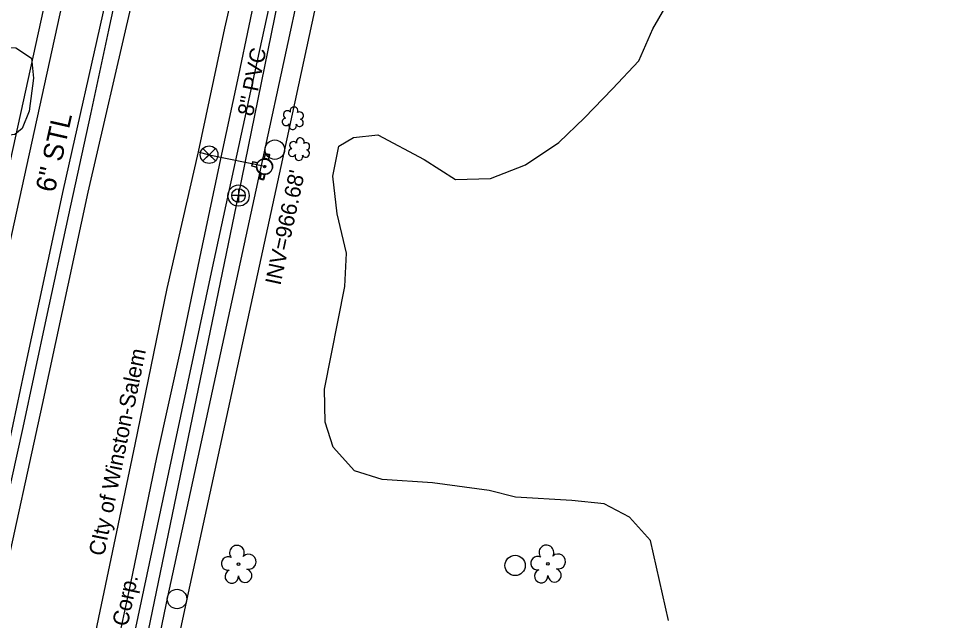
# Model space of a CAD drawing. Extents: x 1614427 to 1617186, y 896524 to 905462.
# Drawn here: x 1616435.3 to 1616671.9, y 900797.8 to 900949.7 of the extents above; entities that cross this region are included whole.
import ezdxf

# ---------------------------------------------------------------- set-up
doc = ezdxf.new("R2010")
doc.units = 0
for name, color, linetype in [('Exist Other Culture Well CELL', 7, 'Continuous'), ('Exist Roads EOP', 7, 'Continuous'), ('Exist Utilities Gas UG Line SUE LOS B', 7, 'Continuous'), ('Exist Utilities Gas UG Line SUE LOS B Text', 7, 'Continuous'), ('Exist Utilities Other Pole CELL', 7, 'Continuous'), ('Exist Utilities Power UG Cable SUE LOS D', 7, 'Continuous'), ('Exist Utilities Sanitary Sewer AG Line Invert Elevation', 7, 'Continuous'), ('Exist Utilities Sanitary Sewer Manhole CELL', 7, 'Continuous'), ('Exist Utilities Sanitary Sewer UG Line', 7, 'Continuous'), ('Exist Utilities Sanitary Sewer UG Line Text', 7, 'Continuous'), ('Exist Utilities Telephone UG Cable SUE LOS B', 7, 'Continuous'), ('Exist Utilities Telephone UG FO SUE LOS B', 7, 'Continuous'), ('Exist Utilities Telephone UG FO SUE LOS B Text', 7, 'Continuous'), ('Exist Utilities Telephone UG FO SUE LOS D', 7, 'Continuous'), ('Exist Utilities TV UG FO Cable SUE LOS D', 7, 'Continuous'), ('Exist Utilities Water Fire Hydrant CELL', 7, 'Continuous'), ('Exist Utilities Water UG Line SUE LOS B', 7, 'Continuous'), ('Exist Utilities Water UG Line SUE LOS B Text', 7, 'Continuous'), ('Exist Utilities Water Valve CELL', 7, 'Continuous'), ('Exist Vegetation Hedge Row', 7, 'Continuous'), ('Exist Vegetation Shrub CELL', 7, 'Continuous'), ('Exist Vegetation Tree CELL', 7, 'Continuous'), ('Exist Vegetation Woods Line', 7, 'Continuous')]:
    doc.layers.add(name, color=color, linetype=linetype)

msp = doc.modelspace()

# ---------------------------------------------------------------- linework, layer by layer
at = {"layer": 'Exist Other Culture Well CELL'}
msp.add_circle((1616560.59, 900811.64), 2.56, dxfattribs=at)
at = {"layer": 'Exist Roads EOP'}
for points in [[(1616506.95, 901008.01), (1616504.02, 900996.97), (1616501.39, 900985.55), (1616496, 900960.38), (1616490.77, 900935.39), (1616486.24, 900914.29), (1616481.23, 900890.84), (1616476.26, 900867), (1616470.04, 900838.9), (1616463.48, 900807.17), (1616456.7, 900775.38), (1616450.29, 900746.19), (1616449.34, 900741.63)], [(1616430.84, 900821.33), (1616436.39, 900846.5), (1616442.3, 900874.05), (1616447.95, 900900.18), (1616453.52, 900925.57), (1616457.99, 900946.8), (1616463.22, 900971)]]:
    msp.add_lwpolyline(points, dxfattribs=at)
at = {"layer": 'Exist Utilities Gas UG Line SUE LOS B'}
msp.add_lwpolyline([(1616457.16, 900954), (1616446.5, 900906.58), (1616436.54, 900860.35), (1616425.39, 900807.83), (1616416.23, 900761.6), (1616413.42, 900748.01), (1616411.61, 900739.4), (1616399.49, 900682.3), (1616394.55, 900660.9), (1616391.55, 900647.56), (1616383.19, 900606.2), (1616371.67, 900559.03), (1616360.02, 900508.87), (1616351.28, 900469.28), (1616341.84, 900429.49), (1616331.7, 900383.47)], dxfattribs=at)
at = {"layer": 'Exist Utilities Other Pole CELL'}
for centre in [(1616499.94, 900916.61), (1616475.24, 900803.17)]:
    msp.add_circle(centre, 2.46, dxfattribs=at)
at = {"layer": 'Exist Utilities Power UG Cable SUE LOS D'}
msp.add_line((1616444.89, 900672.03), (1616472.94, 900803.7), dxfattribs=at)
msp.add_lwpolyline([(1616472.94, 900803.7), (1616497.54, 900917.27), (1616543.86, 901131.07), (1616567.27, 901236.77), (1616608.79, 901427.38), (1616667.35, 901702.61)], dxfattribs=at)
at = {"layer": 'Exist Utilities Sanitary Sewer Manhole CELL'}
msp.add_lwpolyline([(1616490.77, 900906.73), (1616490.77, 900903.3), (1616490.77, 900905.02), (1616492.49, 900905.02), (1616489.06, 900905.02)], dxfattribs=at)
for radius in [2.69, 1.71]:
    msp.add_circle((1616490.77, 900905.02), radius, dxfattribs=at)
at = {"layer": 'Exist Utilities Sanitary Sewer UG Line'}
msp.add_lwpolyline([(1616444.8, 900682.93), (1616490.78, 900905.02), (1616557.11, 901230.35), (1616512.18, 901240.77), (1616568.35, 901492.88)], dxfattribs=at)
at = {"layer": 'Exist Utilities Telephone UG Cable SUE LOS B'}
msp.add_lwpolyline([(1616503.04, 901208.05), (1616504.34, 901207.7), (1616513.47, 901204.29), (1616516.02, 901201.09), (1616509.49, 901166.04), (1616502.86, 901137.25), (1616493.6, 901093.66), (1616483.21, 901045.76), (1616472.94, 900998.19), (1616463.74, 900953.48), (1616452.75, 900905.89), (1616441.22, 900852.26), (1616431.02, 900805.67), (1616418.45, 900757.41), (1616403.67, 900741.28), (1616397.61, 900729.94), (1616386.99, 900684.21), (1616386.12, 900682.91)], dxfattribs=at)
at = {"layer": 'Exist Utilities Telephone UG FO SUE LOS B'}
msp.add_lwpolyline([(1616504.35, 900979.92), (1616494.25, 900933.3), (1616484.09, 900886.8), (1616474.48, 900841.84), (1616464.75, 900795.88), (1616454.35, 900748.64), (1616444.4, 900703.78), (1616437.64, 900664.03), (1616423.47, 900606.59), (1616412.32, 900555.07), (1616402.98, 900510.37), (1616391.52, 900460.55), (1616381.89, 900419.08), (1616372.74, 900375.18)], dxfattribs=at)
at = {"layer": 'Exist Utilities Telephone UG FO SUE LOS D'}
msp.add_lwpolyline([(1616266.21, 900145.33), (1616308.81, 900340.55), (1616349.93, 900531.55), (1616382.65, 900683.55), (1616415.98, 900835.43), (1616458.15, 901027.62), (1616484.99, 901167.15), (1616540.12, 901401.87)], dxfattribs=at)
at = {"layer": 'Exist Utilities TV UG FO Cable SUE LOS D'}
for points in [[(1616152.19, 899610.51), (1616181.4, 899742.23), (1616224.51, 899936.62), (1616270.68, 900144.79), (1616313.06, 900339.79), (1616354.51, 900530.51), (1616387.28, 900682.32), (1616420.05, 900834.14), (1616462.24, 901026.32), (1616489.27, 901166.41), (1616544.61, 901400.99), (1616575.34, 901543.24), (1616671.95, 901701.27)], [(1616351.28, 900220.72), (1616414.71, 900507.45), (1616449.63, 900671.08), (1616477.75, 900802.82), (1616502.4, 900916.25), (1616548.57, 901130.04)]]:
    msp.add_lwpolyline(points, dxfattribs=at)
at = {"layer": 'Exist Utilities Water Fire Hydrant CELL'}
for p, q in [((1616497.29, 900912.24), (1616497.29, 900912.24)), ((1616497.39, 900912.4), (1616497.39, 900912.4))]:
    msp.add_line(p, q, dxfattribs=at)
for points in [[(1616497.26, 900914.22), (1616497.57, 900915.47), (1616498.57, 900915.22), (1616498.25, 900913.94)], [(1616497.28, 900914.38), (1616497.55, 900915.64), (1616498.55, 900915.43), (1616498.28, 900914.14)], [(1616495.56, 900913.2), (1616494.31, 900913.51), (1616494.07, 900912.52), (1616495.31, 900912.2)], [(1616495.63, 900913.3), (1616494.37, 900913.56), (1616494.15, 900912.56), (1616495.41, 900912.29)], [(1616496.33, 900910.51), (1616496.02, 900909.26), (1616497.02, 900909.01), (1616497.33, 900910.28)], [(1616496.5, 900910.63), (1616496.23, 900909.37), (1616497.23, 900909.16), (1616497.5, 900910.45)]]:
    msp.add_lwpolyline(points, dxfattribs=at)
for centre, radius in [((1616497.29, 900912.24), 1.98), ((1616497.39, 900912.4), 1.98), ((1616497.29, 900912.24), 0.243), ((1616497.39, 900912.4), 0.243)]:
    msp.add_circle(centre, radius, dxfattribs=at)
at = {"layer": 'Exist Utilities Water UG Line SUE LOS B'}
for points in [[(1616493.22, 900973.35), (1616487.23, 900947.29), (1616480.58, 900916.03), (1616472.64, 900881.54), (1616464.62, 900842.16), (1616454.64, 900794.87), (1616446.79, 900752.77), (1616446.28, 900750.39), (1616440.01, 900719.87), (1616430.91, 900677.69), (1616418.54, 900626.53), (1616407.93, 900577.61), (1616397.15, 900529.91), (1616384.4, 900474.12), (1616373.54, 900426.18), (1616364.03, 900380.59)], [(1616480.58, 900916.03), (1616483.34, 900915.34), (1616497.39, 900912.4)]]:
    msp.add_lwpolyline(points, dxfattribs=at)
at = {"layer": 'Exist Utilities Water Valve CELL'}
msp.add_lwpolyline([(1616484.92, 900916.92), (1616481.77, 900913.77), (1616483.34, 900915.34), (1616484.92, 900913.77), (1616481.77, 900916.92)], dxfattribs=at)
msp.add_circle((1616483.34, 900915.34), 2.23, dxfattribs=at)
at = {"layer": 'Exist Vegetation Hedge Row'}
msp.add_lwpolyline([(1616355.54, 900953.21), (1616363.72, 900947.6), (1616368.6, 900946.43), (1616376.46, 900946.55), (1616383.19, 900949.57), (1616389.6, 900950.43), (1616396.27, 900949.3), (1616406.57, 900946.03), (1616415.84, 900943.79), (1616428.9, 900942.68), (1616434.53, 900942.33), (1616438.53, 900939.68), (1616439.01, 900934.62), (1616437.91, 900926.31), (1616436.14, 900921.91), (1616434.28, 900920.44), (1616430.72, 900919.99), (1616425.49, 900921.25), (1616371.15, 900933.76), (1616341.09, 900938.96), (1616319.83, 900941.56)], dxfattribs=at)
at = {"layer": 'Exist Vegetation Shrub CELL'}
for p, q in [((1616504.54, 900924.34), (1616504.54, 900924.34)), ((1616506.12, 900916.56), (1616506.12, 900916.56))]:
    msp.add_line(p, q, dxfattribs=at)
for centre, radius, start, end in [((1616503.06, 900925.47), 0.968, 35.8908, 245.4216), ((1616504.77, 900926.38), 0.99, 334.8391, 200.4717), ((1616506.21, 900925.21), 0.929, 284.4567, 126.0861), ((1616502.74, 900923.64), 0.955, 95.1099, 327.9534), ((1616506.18, 900923.41), 0.937, 204.9913, 73.4601), ((1616504.41, 900922.66), 0.984, 151.2797, 21.387), ((1616504.64, 900917.69), 0.968, 35.8908, 245.4216), ((1616506.35, 900918.6), 0.99, 334.8391, 200.4717), ((1616504.32, 900915.86), 0.955, 95.1099, 327.9534), ((1616507.76, 900915.64), 0.937, 204.9913, 73.4601), ((1616507.8, 900917.43), 0.929, 284.4567, 126.0861), ((1616506, 900914.88), 0.984, 151.2797, 21.387)]:
    msp.add_arc(centre, radius, start, end, dxfattribs=at)
at = {"layer": 'Exist Vegetation Tree CELL'}
for p, q in [((1616490.75, 900811.97), (1616490.75, 900811.97)), ((1616568.87, 900812.05), (1616568.87, 900812.05))]:
    msp.add_line(p, q, dxfattribs=at)
for centre in [(1616490.75, 900811.97), (1616568.87, 900812.05)]:
    msp.add_circle(centre, 0.326, dxfattribs=at)
for centre, radius, start, end in [((1616490.36, 900814.85), 1.86, 330.1651, 219.7134), ((1616493.3, 900812.56), 1.9, 257.1011, 134.1999), ((1616568.49, 900814.93), 1.86, 330.1651, 219.7134), ((1616571.42, 900812.64), 1.9, 257.1011, 134.1999), ((1616488.14, 900812.13), 1.73, 62.6636, 279.3457), ((1616566.27, 900812.21), 1.73, 62.6636, 279.3457), ((1616489.05, 900808.85), 1.69, 111.5671, 6.231), ((1616492.42, 900809.07), 1.7, 181.2822, 74.56), ((1616567.17, 900808.93), 1.69, 111.5671, 6.231), ((1616570.55, 900809.15), 1.7, 181.2822, 74.56)]:
    msp.add_arc(centre, radius, start, end, dxfattribs=at)
at = {"layer": 'Exist Vegetation Woods Line'}
msp.add_lwpolyline([(1616599.29, 900797.71), (1616594.73, 900817.95), (1616589.45, 900823.8), (1616583.03, 900827.17), (1616574.9, 900828.05), (1616560.72, 900828.84), (1616554.05, 900830.56), (1616539.71, 900832.51), (1616527, 900833.37), (1616520.04, 900835.53), (1616514.66, 900841.49), (1616512.63, 900847.81), (1616512.5, 900856.16), (1616517.56, 900882.06), (1616518.02, 900890.45), (1616515.67, 900900.4), (1616514.54, 900909.89), (1616516.07, 900917.51), (1616519.76, 900919.64), (1616525.94, 900920.37), (1616537.62, 900914.09), (1616545.52, 900909.07), (1616554.38, 900909.34), (1616563.21, 900912.79), (1616571.59, 900918.42), (1616578.08, 900924.6), (1616585.16, 900931.92), (1616591.83, 900939.06), (1616595.38, 900947.14), (1616603.49, 900961.25)], dxfattribs=at)

# ---------------------------------------------------------------- texts
at = {"layer": 'Exist Utilities Gas UG Line SUE LOS B Text'}
msp.add_text('6" STL', height=5, rotation=77.3199, dxfattribs=at).set_placement((1616444.34, 900905.58))
at = {"layer": 'Exist Utilities Sanitary Sewer AG Line Invert Elevation'}
msp.add_text("INV=966.68'", height=4, rotation=77.7588, dxfattribs=at).set_placement((1616501.33, 900882.18))
at = {"layer": 'Exist Utilities Sanitary Sewer UG Line Text'}
msp.add_text('8" PVC', height=4, rotation=78.4755, dxfattribs=at).set_placement((1616494.37, 900924.86))
at = {"layer": 'Exist Utilities Telephone UG FO SUE LOS B Text'}
msp.add_text('AT&T Corp.', height=4, rotation=78.0525, dxfattribs=at).set_placement((1616459.61, 900781.25))
at = {"layer": 'Exist Utilities Water UG Line SUE LOS B Text'}
msp.add_text('CIty of Winston-Salem', height=4, rotation=78.4948, dxfattribs=at).set_placement((1616456.81, 900813.83))

doc.saveas('drawing.dxf')
